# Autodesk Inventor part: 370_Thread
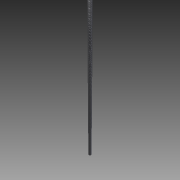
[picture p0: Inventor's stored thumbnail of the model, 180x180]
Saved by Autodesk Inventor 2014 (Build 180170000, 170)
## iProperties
Created: 2013-12
Part Number: 370_Thread
Material: Generic
Document SubType Name: Modeling
Designer: Bram
Density: 1 g/cm^3
Appearance: Default
Author: Bram
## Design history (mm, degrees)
sketch "Sketch1"
  geometry: C1 r 4 at (0, 0); 1 further point
  constraints: 1 centre point, 1 coincident
  dimensions: "d0" = 8 diameter of C1
extrude "Extrusion1" new body sketch "Sketch1" distance "d1" = 370; taper "d2" = 0 deg
thread "Thread1" dims "d3" = 10, "d4" = 0
body "Solid1"
